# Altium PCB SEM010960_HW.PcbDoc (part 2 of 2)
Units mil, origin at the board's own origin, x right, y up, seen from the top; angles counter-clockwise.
Board outline 2559.06 x 1889.76 mil, 2 copper layers (Top Layer, Bottom Layer), stack 62 mil thick; 97 components, 58 nets, 246 pads, 75 vias.
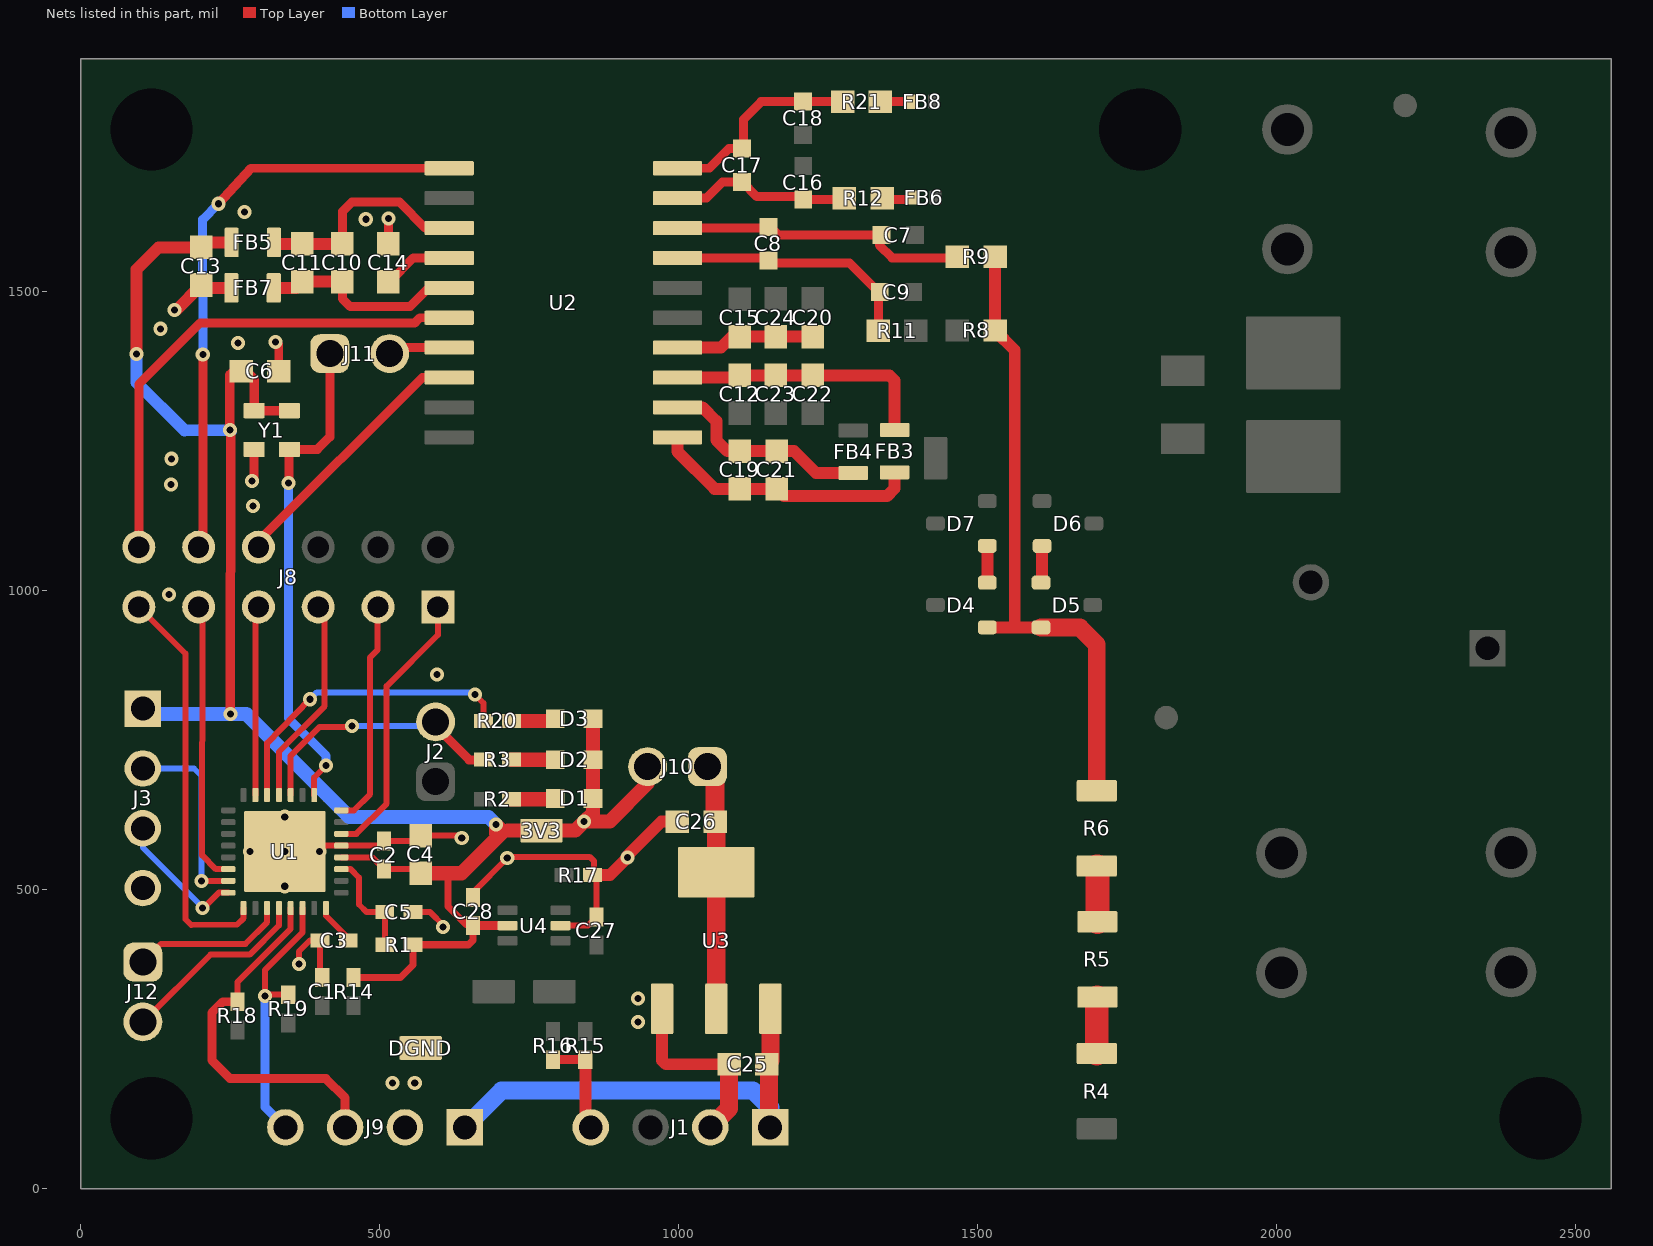
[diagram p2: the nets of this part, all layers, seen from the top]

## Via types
v1: diameter 23.62, hole 11.81, Top Layer to Bottom Layer, 58 vias
v2: diameter 39.37, hole 19.68, Top Layer to Bottom Layer, 12 vias
v3: diameter 23.62, hole 11.81, Top Layer to Bottom Layer, tented both sides, 5 vias

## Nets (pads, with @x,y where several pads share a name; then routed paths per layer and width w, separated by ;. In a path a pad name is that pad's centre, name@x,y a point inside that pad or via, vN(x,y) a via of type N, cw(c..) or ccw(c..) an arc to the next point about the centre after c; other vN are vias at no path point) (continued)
ADC_DVDD: C10.1 C11.2 FB5.1 U2.13 | length 372.5
  Top Layer w10: FB5.1@322.96,1582.83 FB5.1@325.47,1580.32
  Top Layer w15: C10.1@437.16,1580.32 437.16,1634.28 453.14,1650.26 532.82,1650.26 576.17,1606.91 U2.13@615.89,1606.91
  Top Layer w20: FB5.1@325.47,1580.32 C11.2@370.41,1580.32 C10.1@437.16,1580.32
ADC_SCLK: J8.8 U2.18 | length 442.1
  Top Layer w15: J8.8@296.88,1073.2 296.88,1082.81 570.98,1356.91 U2.18@615.89,1356.91
AMC_CLKIN: J11.2 U2.17 | length 106.5
  Top Layer w10: U2.17@613.92,1404.94 U2.17@615.89,1406.91
  Top Layer w15: J11.2@516.29,1396.93 526.27,1406.91 U2.17@615.89,1406.91
AMC_CS0: J8.1 U1.6 | length 461.2
  Top Layer w10: U1.6@435.43,593.76 460.76,593.76 511.4,644.39 511.4,840.9 596.88,926.38 J8.1@596.88,973.2
AMC_D\R\D\Y\: J8.12 U2.16 | length 837.3
  Top Layer w15: J8.12@96.88,1073.2 96.88,1345.32 199.88,1448.33 558.17,1448.33 559.07,1449.23 559.18,1449.23 566.85,1456.91 U2.16@615.89,1456.91
AMC_D\R\D\Y\0: J8.11 U1.25 | length 677.2
  Top Layer w10: J8.11@96.88,973.2 174.95,895.14 174.95,450.95 184.51,441.39 261.07,441.8 272.05,452.78 U1.25@272.05,469.74
AMC_SYNC_RESET: J8.10 U2.11 | length 1004
  Top Layer w15: J8.10@196.88,1073.2 203.84,1080.16 v1(203.84,1395.2) v1@203.57,1394.93 ; v1(230.06,1647.5) 284.34,1706.91 U2.11@615.89,1706.91
  Bottom Layer w15: v1@206.26,1392.77 v1(203.84,1395.2) 203.84,1416.57 203.59,1620.97 v1(230.06,1647.5)
AMC_SYNC_RESET0: J8.9 U1.22 | length 471.6
  Top Layer w10: J8.9@196.88,973.2 203.57,966.52 203.57,938.7 202.64,557.77 225.7,534.7 U1.22@246.46,534.7
DCDC_HGND: C19.2 C21.1 FB4.1 U2.2 | length 357.6
  Top Layer w20: U2.2@997.78,1306.91 1039.55,1306.91 1062.59,1283.86 1062.59,1252.34 1081.14,1233.79 C19.2@1101.57,1233.79 C21.1@1163.8,1233.79 1192.71,1233.79 1229.13,1197.37 FB4.1@1291.55,1197.37
DCDC_OUT: C19.1 C21.2 FB3.1 U2.1 | length 451.3
  Top Layer w10: C19.1@1100.23,1169.46 C19.1@1101.57,1170.8
  Top Layer w20: U2.1@997.78,1256.91 997.78,1232.92 1059.9,1170.8 1098.9,1170.8 C19.1@1100.23,1169.46 ; C19.1@1101.57,1170.8 C21.2@1163.8,1170.8 1176.03,1158.56 1348.04,1158.56 1360.91,1171.43 FB3.1@1360.91,1198.36
DGND: C1.2 C2.2 C3.1 C4.1 C5.2 C6.2 C13.1 C14.2 C25.2 C26.2 C27.2 C28.2 DGND.1 FB7.2 J1.2 J3.4 J9.2 R17.1 U1.5 U1.33 U3.1 U4.2 Y1.2 | length 1711.5
  Top Layer w10: v1(156.26,1469.6) v1@159.47,1469.6 ; C13.1@201.52,1511.65 C13.1@206.26,1506.91 ; v3(282.87,564.23) v3(340.94,622.3) ; v1(364.43,376.01) 364.43,396.97 382.77,415.31 C3.1@399.87,415.31 399.87,357.34 C1.2@403.54,353.67 ; v3(399.02,564.23) 408.86,574.07 U1.5@435.43,574.07 498.9,574.07 C2.2@506.78,581.95 559.28,581.95 C4.1@568.12,590.78 632.61,590.78 v1(636.88,586.52) ; C5.2@555.4,462.82 584.13,462.82 v1@606.48,440.47 ; v1@600.06,438.18 v1@611.11,438.18 ; C28.2@655.94,487.46 655.94,496.3 v1(712.97,553.34) 715.08,555.44 850.95,555.44 857.75,548.63 857.75,527.25 R17.1@855.34,524.84 862.2,517.97 C27.2@862.2,454.95 847.64,440.38 U4.2@802.02,440.38
  Top Layer w15: v1(285.83,1183.59) 289.62,1187.39 Y1.2@289.62,1236.61 ; v1(325.47,1416.57) 330.86,1411.17 C6.2@330.86,1367.63 ; C14.2@514.1,1580.32 v1(514.1,1622.96)
  Top Layer w19.68: R17.1@855.34,524.84 884.69,524.84 v1(914.24,554.39) 914.24,558.01 970.51,614.27 C26.2@1005.61,614.27
  Top Layer w20: v1@159.47,1469.6 C13.1@201.52,1511.65 ; C13.1@206.26,1506.91 FB7.2@251.55,1506.91 ; U3.1@972.04,301.14 972.04,214.71 978.33,208.42 C25.2@1084.11,208.42
  Top Layer w30: J1.2@1052.59,92.71 J1.2@1052.59,102.93 1084.11,134.44 C25.2@1084.11,204.54
  other v1: 520.98,177.22 558.3,177.22 931.38,279.35 931.38,318.23 605.59,438.18 595.38,860.16 147.33,994.09 287.78,1142.31 150.66,1178.04 151.6,1221 262.44,1414.66 133.07,1438.39 476.44,1621.64 273.68,1633.99
  other v3: 340.94,506.16 340.94,564.23
DGND_AMC: C10.2 C11.1 FB7.1 U2.15 | length 344.7
  Top Layer w15: C10.2@437.16,1517.33 437.19,1488.84 450.43,1475.61 550.22,1475.61 581.52,1506.91 U2.15@615.89,1506.91
  Top Layer w20: FB7.1@322.42,1506.91 359.99,1506.91 C11.1@370.41,1517.33 C10.2@437.16,1517.33
GLED: D1.1 R2.2 | length 73.5
  Top Layer w10: D1.1@791.85,651.64 D1.1@793.25,653.05
  Top Layer w23.62: R2.2@720.32,651.64 D1.1@791.85,651.64
HLDO_IN: C12.2 C22.1 C23.1 FB3.2 U2.3 | length 459.6
  Top Layer w10: C12.2@1107.52,1356.91 C12.2@1110.37,1354.06 ; C22.1@1224.17,1360.57 C22.1@1224.41,1360.32
  Top Layer w20: U2.3@997.78,1356.91 C12.2@1107.52,1356.91 ; C12.2@1101.57,1360.57 1163.8,1360.57 C22.1@1224.17,1360.57 1352.03,1360.57 1360.91,1351.69 FB3.2@1360.91,1269.22
HLDO_OUT: C15.2 C20.1 C24.1 U2.4 | length 242.2
  Top Layer w10: C24.1@1158.15,1424.51 1158.66,1425.02 C24.1@1165.81,1425.02 ; C20.1@1219.72,1425.02 C20.1@1220.11,1425.41
  Top Layer w20: U2.4@997.78,1406.91 1070.23,1406.91 1088.34,1425.02 C15.2@1101.57,1425.02 1101.96,1425.41 C24.1@1162.23,1425.41 1220.11,1425.41 C20.1@1223.92,1425.41
IN1: C17.2 C18.2 R21.2 U2.10 | length 350.6
  Top Layer w15: U2.10@997.78,1706.91 1050.94,1706.91 1084.15,1740.12 C17.2@1105.92,1740.12 1108.23,1742.43 1108.23,1788.71 1137.69,1818.18 C18.2@1207.7,1818.18 R21.2@1274.02,1818.18 R21.2@1275.22,1818.18
IP1: C16.1 C17.1 R12.2 U2.9 | length 305.5
  Top Layer w15: U2.9@997.78,1656.91 1045.88,1656.91 1073.09,1684.12 C17.1@1105.92,1684.12 1130.59,1659.44 1203.07,1659.44 C16.1@1207.99,1654.52 1279.47,1654.52 R12.2@1279.7,1654.75
LMK_CLKOUT: J11.1 U1.10 Y1.3 | length 824.4
  Top Layer w10: U1.10@390.16,658.72 390.16,687.96 v1(409.96,707.77)
  Top Layer w15: v1(346.88,1180.64) 348.38,1182.14 348.38,1229.11 355.88,1236.61 395.33,1236.61 416.29,1257.57 J11.1@416.29,1396.93
  Bottom Layer w15: v1(346.88,1180.64) 346.88,787.32 409.96,724.24 v1(409.96,707.77)
M_BUS: J1.4 R15.2 R16.2 | length 171.1
  Top Layer w15: R16.2@789.37,216.09 R15.2@843.53,216.09
  Top Layer w20: R15.2@843.53,216.09 843.53,111.99 J1.4@852.59,102.93
MCU_Status: R20.1 U1.14 | length 521.3
  Top Layer w10: U1.14@311.42,658.72 311.42,745.39 v1(383.04,818.9) ; v1(658.81,826.82) 673.08,812.54 R20.1@673.08,782.68
  Bottom Layer w10: v1(383.04,818.9) 394.5,830.36 655.27,830.36 v1(658.81,826.82)
NetC14_1: C14.1 U2.14 | length 118.2
  Top Layer w10: C14.1@514.1,1517.33 C14.1@516.23,1517.33
  Top Layer w15: C14.1@516.23,1517.33 555.81,1556.91 U2.14@615.89,1556.91
NetD3_1: D3.1 R20.2 | length 74.4
  Top Layer w23.62: R20.2@720.32,782.68 789.72,782.68 D3.1@793.25,786.21
NetD4_1: D4.1 D5.2 R6.2 R8.2 R9.1 | length 1072.9
  Top Layer w20: D4.1@1515.87,939.03 1561.75,939.03 ; R9.1@1528.77,1558.67 R8.2@1528.77,1435.59 1561.75,1402.61 1561.75,939.03 ; D5.2@1605.59,939.03 1561.75,939.03
  Top Layer w30: D5.2@1605.59,939.03 1670.55,939.03 1698.88,910.7 R6.2@1698.88,665.89
NetD4_2: D4.2 D7.1 | length 61.5
  Top Layer w20: D4.2@1515.87,1013.84 D7.1@1515.87,1075.35
NetD5_1: D5.1 D6.2 | length 62.3
  Top Layer w10: D5.1@1605.59,1013.84 D5.1@1607.47,1015.71
  Top Layer w20: D5.1@1607.47,1015.71 D6.2@1607.47,1075.35
NetFB6_1: FB6.1 R12.1 | length 55.3
  Top Layer w15: R12.1@1335.7,1654.75 1386.79,1654.75 FB6.1@1389.74,1657.7
NetFB8_1: FB8.1 R21.1 | length 50.2
  Top Layer w15: R21.1@1337.01,1818.18 FB8.1@1387.21,1818.18
NetR4_1: R4.1 R5.2 | length 94.6
  Top Layer w39.37: R5.2@1698.88,319.64 R5.2@1699.92,320.68
  Top Layer w40: R4.1@1698.88,226.56 R5.2@1698.88,319.64
NetR5_1: R5.1 R6.1 | length 93.7
  Top Layer w39.37: R6.1@1698.88,539.91 R6.1@1699.92,538.86
  Top Layer w40: R5.1@1699.92,446.67 R6.1@1699.92,538.86
nRST: C5.1 R1.1 U1.3 | length 183.4
  Top Layer w10: U1.3@435.43,534.7 451,534.7 465.08,520.63 465.08,475.65 477.9,462.82 C5.1@508.16,462.82 R1.1@508.16,408.3
REACT: J2.2 R3.1 U1.12 | length 428.3
  Top Layer w10: U1.12@350.79,658.72 350.79,724.21 399.23,772.65 v1@444.56,772.65
  Top Layer w15: J2.2@593.26,781.01 593.26,773.44 649.08,717.62 R3.1@668.73,717.62
  Bottom Layer w10: v1(453.14,774.42) 586.67,774.42 J2.2@593.26,781.01
SPI0_PICO: J8.5 U1.13 | length 350.7
  Top Layer w10: U1.13@330.99,658.83 330.99,730.55 407.64,807.19 407.64,808.58 407.73,808.67 407.73,829.12 407.64,829.21 407.64,962.45 J8.5@396.88,973.2
SPI0_POCI: J8.3 U1.8 | length 378
  Top Layer w10: U1.8@435.43,633.13 456.71,633.13 483.74,660.15 483.74,889.05 496.2,901.51 496.2,972.52 J8.3@496.88,973.2
SPI0_SCK: J8.7 U1.15 | length 316.7
  Top Layer w10: U1.15@291.73,658.72 291.73,692.98 291.61,693.1 291.61,967.93 J8.7@296.88,973.2
SWCLK: J3.3 U1.24 | length 228.8
  Top Layer w10: v1(203.09,469.74) 205.66,469.74 205.66,470.19 230.8,495.33 U1.24@246.46,495.33
  Bottom Layer w10: J3.3@103.57,603.05 103.57,570.87 203.09,471.35 v1(203.09,469.74)
SWDIO: J3.2 U1.23 | length 323.7
  Top Layer w10: v1(201.6,515.02) 205.37,515.02 205.51,514.88 205.66,515.02 U1.23@246.46,515.02
  Bottom Layer w10: J3.2@103.57,703.05 189.07,703.05 201.6,690.53 v1(201.6,515.02)
UART_RX1_GUI: J12.2 U1.28 | length 322.8
  Top Layer w10: J12.2@104.32,279.33 216.66,391.67 282.28,391.67 331.1,440.49 U1.28@331.1,469.74
UART_RX2_HOST: J9.3 R18.1 U1.29 | length 619.7
  Top Layer w10: R18.1@257.12,308.39 R18.1@261.68,312.95 ; R18.1@262.19,321.02 262.19,346.3 350.79,434.9 U1.29@350.79,469.74
  Top Layer w15: R18.1@261.68,312.95 237.51,312.95 219.09,294.52 219.09,215.14 249.68,184.55 409.67,184.55 441.91,152.32 J9.3@441.91,102.93
UART_TX1_GUI: J12.1 U1.27 | length 259.2
  Top Layer w10: J12.1@103.57,379.33 133.78,409.54 274.88,409.54 311.42,446.08 U1.27@311.42,469.74
UART_TX2_HOST: J9.4 R19.1 U1.30 | length 447
  Top Layer w10: R19.1@346.85,324.76 309.65,324.76 v1(307.68,322.79) 307.68,365.71 370.47,428.51 U1.30@370.47,469.74
  Bottom Layer w15: v1(307.68,322.79) 307.68,137.15 J9.4@341.91,102.93
VCORE: C3.2 U1.32 | length 69.9
  Top Layer w10: U1.32@409.84,469.74 409.84,456.78 447.11,419.52 C3.2@447.11,415.31
VDD1_3V3: C26.1 J10.1 U3.2 U3.4 | length 411.1
  Top Layer w31.5: J10.1@1047.78,706.13 1060.62,693.29 C26.1@1060.62,614.27 1062.59,612.3 U3.4@1062.59,529.48 U3.2@1062.59,301.14
VDD_3V3: 3V3.1 C2.1 C4.2 C6.1 C13.2 C28.1 D1.2 D2.2 D3.2 FB5.2 J3.1 J10.2 R1.2 R14.2 U1.4 U4.5 Y1.1 Y1.4 | length 3252.7
  Top Layer w10: v1(93.25,1396.53) v1@94.53,1397.82 ; C13.2@201.52,1574.64 C13.2@209.7,1582.83 ; U1.4@435.43,554.39 487.09,554.39 C2.1@506.78,534.7 561.21,534.7 C4.2@568.12,527.79 ; C28.1@655.94,440.22 C28.1@656.11,440.38
  Top Layer w11.81: R14.2@455.94,353.67 534.54,353.67 555.4,374.52 R1.2@555.4,408.3 648.41,408.3 655.94,415.84 C28.1@655.94,440.22 ; 614.19,523.94 614.19,472.13 C28.1@644.13,442.18
  Top Layer w15: C28.1@656.11,440.38 U4.5@713.44,440.38
  Top Layer w15.75: v1@246.06,1272.04 v1(249.22,1268.88) 249.22,1361.64 260.73,1373.15 270.69,1373.15 289.62,1354.21 Y1.1@289.62,1301.57 Y1.4@348.68,1301.57 ; v1(250.08,794.49) v1@250.83,1267.29
  Top Layer w20: v1(93.25,1396.53) 93.25,1538 129.89,1574.64 C13.2@201.52,1574.64 ; C13.2@209.7,1582.83 FB5.2@252.1,1582.83
  Top Layer w23.62: C4.2@568.12,527.79 636.55,527.79 703.52,594.76 ; 694.09,594.76 v1(694.09,609.64) 704.45,599.28 ; 713.88,599.28 826.67,599.28 ; 3V3.1@770.28,599.28 826.67,599.28 ; D2.2@856.23,717.62 856.23,653.05 856.24,628.84 v1(841.67,614.27) ; D2.2@856.23,717.62 D3.2@856.24,786.21 ; J10.2@947.78,706.13 947.78,677.67 884.38,614.27 v1(841.67,614.27) ; 826.67,599.28 v1(841.67,614.27)
  Bottom Layer w20: v1(93.25,1396.53) 93.25,1348.43 173.16,1268.52 v1(249.22,1268.88) v1@250.83,1267.29
  Bottom Layer w23.62: J3.1@103.57,803.05 112.13,794.49 v1(250.08,794.49) 276.45,794.49 448.82,622.13 681.6,622.13 v1(694.09,609.64)
VIN: C25.1 J1.1 J9.1 U3.3 | length 784.3
  Top Layer w10: C25.1@1147.1,208.42 C25.1@1153.14,214.46
  Top Layer w20: C25.1@1147.1,208.42 C25.1@1150.56,204.97 ; J1.1@1150.56,104.96 J1.1@1152.59,102.93
  Top Layer w30: J1.1@1150.56,104.96 C25.1@1150.56,204.97 ; C25.1@1153.14,214.46 U3.3@1153.14,301.14
  Bottom Layer w30: J9.1@641.91,102.93 703.67,164.69 1124.11,164.69 1152.59,136.21
  Bottom Layer w31.5: J1.1@1152.59,102.93 1152.59,136.21
VN2: C8.2 C9.2 R11.2 U2.7 | length 425.3
  Top Layer w15: U2.7@997.78,1556.91 1141.82,1556.91 1149.9,1548.83 1285.17,1548.83 1334.09,1499.91 1334.09,1435.59 R11.2@1333.36,1434.86
VP2: C7.1 C8.1 R9.2 U2.8 | length 504
  Top Layer w15: U2.8@997.78,1606.91 1144.99,1606.91 1149.9,1611.82 1166.7,1595.02 1335.41,1595.02 1335.41,1578.23 1356.73,1556.91 1459.91,1556.91 R9.2@1465.06,1562.05
YLED: D2.1 R3.2 | length 73.1
  Top Layer w23.62: R3.2@720.32,717.94 720.64,717.62 D2.1@793.24,717.62
pads on no net: D4.3 D5.3 D6.1 D7.2 FID1.1 FID2.1 J1.3 MH1.1 MH2.1 MH3.1 MH4.1 U1.1 U1.2 U1.7 U1.9 U1.16 U1.17 U1.18 U1.19 U1.20 U1.21 U1.26 U1.31

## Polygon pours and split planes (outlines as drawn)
DGND on Top Layer "TOP_LAYER_DGND_P033" (solid, remove dead copper, pour order 33): 38.81,1558.32 305.12,1824.63 644.07,1824.63 644.07,1101.79 928.15,817.71 1053.64,817.71 1291.55,579.8 1291.55,39.96 323.61,39.96 38.81,324.76
A_Netural_IN on Top Layer "TOP_LAYER_A_NETURAL_IN_P031" (solid, remove dead copper, pour order 31): 981.4,1846.72 1452.87,1846.72 1452.87,1716.97 1579.52,1716.97 1701.01,1595.48 1701.01,1322.55 1747.17,1276.4 2102.36,1276.4 2102.36,904.09 1448.3,904.09 1210.08,1142.31 1060.97,1142.31 978.69,1224.59 978.69,1842.2 983.21,1846.72
VDD1_3V3 on Top Layer "TOP_LAYER_VDD1_3V3_P027" (solid, remove dead copper, pour order 27): 1000,738.44 1001.15,739.6 1093.95,739.6 1093.95,589.53 1090.15,585.73 1092.55,583.33 1128.77,583.33 1128.77,401.75 1127.02,403.5 1000,403.5
VDD_3V3 on Top Layer "TOP_LAYER_VDD_3V3_P026" (solid, remove dead copper, pour order 26): 816.86,745.18 983.85,745.18 983.85,684.47 882.7,583.33 674.56,583.33 674.56,628.29 677.36,625.49 816.87,625.49 816.87,745.18
A_Netural_OUT on Top Layer "TOP_LAYER_A_NETURAL_OUT_P004" (solid, remove dead copper, pour order 4): 1781.5,1642.74 1956.5,1817.74 1956.5,1832.72 2102.36,1832.72 2102.36,1346.64 1781.5,1346.64
DGND on Bottom Layer "BOTTOM_LAYER_DGND_P038" (solid, remove dead copper, pour order 38): 30.89,1522.08 328.48,1819.67 328.48,1824.63 644.07,1824.63 645.16,1823.54 645.16,1131.58 675.69,1101.05 675.69,1072.28 928.24,819.72 1051.62,819.72 1291.55,579.8 1291.55,39.96 323.61,39.96 46.89,316.68 46.89,1511.53 30.89,1527.53
A_Netural_IN on Bottom Layer "BOTTOM_LAYER_A_NETURAL_IN_P032" (solid, remove dead copper, pour order 32): 981.4,1846.72 982.74,1845.38 1511.52,1845.38 1748.72,1608.18 1748.72,1277.95 1747.17,1276.4 2102.36,1276.4 2102.36,904.09 1448.3,904.09 1210.08,1142.31 1074.3,1142.31 1074.3,1143.28 983.21,1234.37 983.21,1846.72
A_Netural_OUT on Bottom Layer "BOTTOM_LAYER_A_NETURAL_OUT_P014" (solid, remove dead copper, pour order 14): 1781.5,1641.74 1972.48,1832.72 2102.36,1832.72 2102.36,1346.64 1781.5,1346.64

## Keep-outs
Keep-Out Layer:
  text ".Layer_Name" at 577,-858.49 h60

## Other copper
Top Layer:
  pour cut-out: 265.75,1328.74 267.89,1330.89 384.98,1330.89 384.98,1202.93 385.47,1202.45 385.31,1202.29 266.09,1202.29 266.09,1328.09
  text ".Layer_Name" at 577,-858.49 h60
Bottom Layer:
  pour cut-out: 267.89,1330.89 384.98,1330.89 384.98,1202.93 384.34,1202.29 266.09,1202.29 266.09,1329.08
  text ".Layer_Name" at 577,-858.49 h60

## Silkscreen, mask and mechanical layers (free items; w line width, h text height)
Top Overlay:
  lines w10: 500.81,791.44 500.81,767.82 525.53,743.1 ; 1261.38,1399.8 1417.8,1398.07 1441.01,1374.86 ; 1411.85,1462.06 1417.41,1462.06 1433.79,1478.45
  text "Rev_A" at 881.99,1791.6 h60
  text "TIDA-010960" at 291.61,1781.85 h108.27
  text "3V3" at 11.94,867.88 h60 r270
  text "REACT" at 410.26,844.18 h50
  text "ACT" at 424.21,800.75 h50
  text "DIO" at 11.69,758.29 h60 r270
  text "CLK" at 11.69,654.41 h60 r270
  text "GND" at 11.69,543.66 h60 r270
  text "TX1" at 11.6,418.17 h60 r270
  text "RX1" at 11.6,311.72 h60 r270
  text "GND" at 502.14,12.57 h60
  text "VIN" at 626.33,12.57 h60
  text "MBUS" at 786.04,12.57 h60
  text "GND" at 984.47,12.57 h60
  text "VIN" at 1119.02,12.57 h60
  text "TX2" at 286.88,12.49 h60
  text "RX2" at 397.76,12.49 h60
  text ".Layer_Name" at 577,-858.49 h60
Bottom Overlay:
  text ".Layer_Name" at 577,-858.49 h60
Top Paste:
  text ".Layer_Name" at 577,-858.49 h60
Bottom Paste:
  text ".Layer_Name" at 577,-858.49 h60
Top Solder:
  text ".Layer_Name" at 577,-858.49 h60
  text ".Layer_Name" at 577,-858.49 h60
Bottom Solder:
  text ".Layer_Name" at 577,-858.49 h60
Drill Guide:
  text ".Layer_Name" at 577,-858.49 h60
M1 Board Outline:
  the board outline again, w10
  text ".Layer_Name" at 577,-858.49 h60
M2 Board Dimensions:
  rectangle: 0,-275 125,-150
  rectangle: 125,-400 500,-275
  lines w7: 0,-275 1000,-275 ; 125,-400 125,-150 ; 250,-400 250,-150 ; 500,-400 500,-150 ; 750,-400 750,-150 ; 0,-400 1000,-400 1000,-150 0,-150 0,-400
  text ".Layer_Name" at 577,-858.49 h60
M3 3D STEP Top:
  text ".Layer_Name" at 577,-858.49 h60
M4 3D STEP Bottom:
  text ".Layer_Name" at 577,-858.49 h60
M5 Assembly Top:
  lines w10: -292,-930.17 6308,-930.17 ; -292,-726.83 6310,-726.83 ; -292,-523.5 -292,-1133.5 3713,-1133.5 6310,-1133.5 6310,-523.5 -291.5,-523.5 -291.5,-1133.5 1284,-1133.5 ; 2173,-1133.5 2173,-523.5 ; 3440,-726.83 3440,-523.5 ; 4280,-726.83 4280,-523.5 ; 4902,-1140 4902,-937.17
  text ".VariantName" at 1618.2,-275 h60
  text "COMPONENTS MARKED 'DNP' SHOULD NOT BE POPULATED." at 2233.07,-433.07 h60
  text "ASSEMBLY VARIANT:" at 1153,-434 h60
  text "PCB VIEWED FROM TOP SIDE" at -228.5,-655.67 h60
  text "BOARD #:" at 2248,-655.67 h60
  text ".PRJ_Number" at 2793.5,-655.67 h60
  text "REV:" at 3638,-655.67 h60
  text ".PCB_Rev" at 3929.5,-655.67 h60
  text "SVN REV:" at 4476,-655.67 h60
  text ".VersionControl_RevNumber" at 4982,-655.67 h60
  text "TID #:" at 2248,-859 h60
  text ".TID" at 2793.5,-859 h60
  text "PLOT NAME =" at -228.5,-1064.34 h60
  text ".plot_File_Name" at 577,-1064.34 h60
  text "GENERATED    :" at 2250,-1064.34 h60
  text ".Print_Date" at 3119.5,-1064.34 h60
  text ".Print_Time" at 3848.5,-1064.34 h60
  text "TEXAS INSTRUMENTS" at 5113,-1064.34 h60
M6 Assembly Bottom:
  lines w10: -292.5,-727.33 6309.5,-727.33 ; -290.5,-930.67 6309.5,-930.67 ; 1115.5,-1140.5 1115.5,-937.67 ; 1737.5,-727.33 1737.5,-524 ; 2577.5,-727.33 2577.5,-524 ; 3539.38,-1135.29 3539.38,-525.29 ; 4733.5,-1134 6309,-1134 6309,-524 -292.5,-524 -292.5,-1134 2304.5,-1134 6309.5,-1134 6309.5,-524
  text "COMPONENTS MARKED 'DNP' SHOULD NOT BE POPULATED." at 5324.8,-265.75 h60
  text ".VariantName" at 5058,-434 h60
  text "ASSEMBLY VARIANT:" at 6097,-434 h60
  text ".VersionControl_RevNumber" at 1035.5,-656.17 h60
  text "SVN REV:" at 1541.5,-656.17 h60
  text ".PCB_Rev" at 2088,-656.17 h60
  text "REV:" at 2379.5,-656.17 h60
  text ".PRJ_Number" at 3224,-656.17 h60
  text "BOARD #:" at 3769.5,-656.17 h60
  text "PCB VIEWED FROM BOTTOM SIDE" at 6246,-656.17 h60
  text ".TID" at 3224,-859.5 h60
  text "TID #:" at 3769.5,-859.5 h60
  text "TEXAS INSTRUMENTS" at 904.5,-1064.84 h60
  text ".Print_Time" at 2169,-1064.84 h60
  text ".Print_Date" at 2898,-1064.84 h60
  text "GENERATED    :" at 3767.5,-1064.84 h60
  text ".plot_File_Name" at 5440.5,-1064.84 h60
  text "PLOT NAME =" at 6246,-1064.84 h60
M9 Title Sheet:
  drawing of 57 lines, arcs and shapes, not listed
  text "1" at 739.84,8036.5 h70
  text "2" at 3235.5,8036.5 h70
  text "3" at 5724.84,8036.5 h70
  text "4" at 8231.51,8036.5 h70
  text "5" at 10730.5,8036.5 h70
  text "6" at 13235.5,8036.5 h70
  text "A" at -416.5,6893.5 h70
  text "A" at 14383.5,6893.5 h70
  text "B" at -416.5,4513.5 h70
  text "B" at 14383.5,4513.5 h70
  text "C" at -416.5,2138.5 h70
  text "C" at 14383.5,2138.5 h70
  text "PROJECT TITLE:" at 11343.5,277.5 h45
  text ".PRJ_Title" at 11393.5,144.17 h70
  text "DESIGNED FOR:" at 11343.5,-23.5 h45
  text ".PRJ_Customer" at 11393.5,-163.5 h70
  text "D" at -416.5,-231.5 h70
  text "D" at 14383.5,-231.5 h70
  text "FILE NAME:" at 11343.5,-323.5 h45
  text ".PCB_File_Name_No_Path" at 11393.5,-443.5 h70
  text "Texas Instruments (TI) and/or its licensors do not warrant the accuracy or completeness of this specification" at 6374,-605.34 h45
  text "ENGINEER:" at 11343.5,-613.5 h45
  text "LAYOUT BY:" at 12848.5,-613.5 h45
  text "or any information contained therein. TI and/or its licensors do not warrant that this design will meet" at 6329.01,-718 h45
  text ".PRJ_Engineer" at 11393.5,-768.49 h70
  text "Joe Wang" at 12899,-768.49 h70
  text "the specifications, will be suitable for your application or fit for any particular purpose, or will operate in" at 6329.01,-830.67 h45
  text ".Layer_Name" at 577,-858.49 h60
  text "ALTIUM DESIGNER VERSION:" at 12848.5,-923.5 h45
  text "an implementation. TI and/or its licensors do not warrant that the design is production worthy. You should" at 6329.01,-943.33 h45
  text "completely validate and test your design implementation to confirm the system functionality for your application." at 6374,-1056 h45
  text ".print_Scale" at 11393.5,-1056.83 h70
  text ".Application_BuildNumber" at 12899,-1056.83 h70
  text "1" at 739.84,-1263.5 h70
  text "2" at 3235.5,-1263.5 h70
  text "3" at 5724.84,-1263.5 h70
  text "4" at 8231.51,-1263.5 h70
  text "5" at 10730.5,-1263.5 h70
  text "6" at 13235.5,-1263.5 h70
M10 Fab Notes:
  drawing of 189 lines, arcs and shapes, not listed
  text "DESIGN INFORMATION" at 12382.02,6356.17 h60
  text "MIN. TRACK WIDTH:" at 11737.46,6224.05 h60
  text "8" at 12833.7,6224.05 h60
  text "MIL" at 12988.46,6224.05 h60
  text "7.874" at 12667.32,6102.36 h60
  text "MIN. CLEARANCE:" at 11737.46,6099.92 h60
  text "MIL" at 12988.46,6099.92 h60
  text "MIN. VIA PAD SIZE:" at 11737.46,5975.8 h60
  text "24" at 12803.71,5975.8 h60
  text "MIL" at 12988.46,5975.8 h60
  text "0.05mm (2MIL)" at 12432.46,5845.9 h60
  text "MINIMUM ANNULAR RING" at 11408.23,5837.67 h60
  text "EXTERNAL" at 13140.46,5837.67 h60
  text "PER" at 11608.23,5727.55 h60
  text "IPC-D-275 CLASS 2 LEVEL C" at 11828.23,5727.54 h60
  text "MIL, HOLES" at 13316.46,5627.07 h60
  text "+/-" at 12924,5618.48 h60
  text "+/-" at 13778,5618.48 h60
  text "REGISTRATION TOLERANCES:" at 11408.23,5617.42 h60
  text "METAL" at 12608,5617.42 h60
  text "5" at 13184.2,5617.42 h60
  text "3" at 14017.2,5617.42 h60
  text "MIL" at 14133.46,5617.42 h60
  text "HOLE SIZE TOLERANCE (UNLESS OTHERWISE SPECIFIED):" at 11408.23,5519.1 h60
  text "+/-" at 13778,5516.23 h60
  text "3" at 14017.2,5515.17 h60
  text "MIL" at 14133.46,5515.17 h60
  text "MATERIAL:" at 11333.46,5377.52 h60
  text "FR-4 High Tg" at 12319.9,5249 h60
  text "X" at 12175.46,5241.01 h60
  text "FR-4" at 11754.46,5236.49 h60
  text "OTHER" at 13242.46,5236.49 h60
  text "62 MIL (1.6mm) +/-10%" at 12074.56,5093.46 h60
  text "X" at 11954.46,5091.01 h60
  text "THICKNESS:" at 11408.23,5085.24 h60
  text "OTHER" at 13359.46,5085.24 h60
  text "TOLERANCE:" at 11408.23,4946.92 h60
  text "X" at 12256.46,4946.92 h60
  text "ANSI IPC-6012 TYPE 3 CLASS 2" at 12434.48,4946.92 h60
  text "OTHER +/-" at 12434.46,4802.73 h60
  text "BOW & TWIST:" at 11408.23,4657.54 h60
  text "X" at 12256.46,4657.54 h60
  text "ANSI IPC-6012 TYPE 3 CLASS 2" at 12434.48,4657.54 h60
  text "OTHER +/-" at 12434.46,4510.85 h60
  text "DRILLING:" at 11333.46,4380.23 h60
  text "NC_DRILL FILES" at 13094.46,4275.04 h60
  text "REFERENCE:" at 11408.23,4271.1 h60
  text "X" at 12065.46,4271.01 h60
  text "AS SHOWN" at 12243.46,4271.1 h60
  text "X" at 12966.46,4271.1 h60
  text "OTHER" at 13392.46,4128.85 h60
  text "PTH COPPER THICKNESS:" at 11407.91,4125.32 h60
  text "X" at 12547.14,4125.32 h60
  text "20-30 um" at 12675.14,4125.32 h60
  text "BOARD FINISH:" at 11333.46,3977.73 h60
  text "SILKSCREEN:" at 11488.68,3867.6 h60
  text "X" at 12446.46,3867.6 h60
  text "TOP" at 12563.46,3867.6 h60
  text "X" at 12956.46,3867.6 h60
  text "BOTTOM" at 13074.46,3867.6 h60
  text "SILKSCREEN COLOR:" at 11488.68,3712.41 h60
  text "X" at 12445.46,3712.41 h60
  text "WHITE" at 12563.46,3712.41 h60
  text "OTHER" at 13074.46,3712.41 h60
  text "X" at 12576.46,3568.96 h60
  text "GREEN" at 12694.46,3568.96 h60
  text "OTHER" at 13312.46,3568.96 h60
  text "SOLDER RESIST COLOR:" at 11488.68,3562.1 h60
  text "X" at 12576.46,3414.71 h60
  text "MATTE" at 12694.46,3414.71 h60
  text "SEMI-GLOSS" at 13312,3414.07 h60
  text "IMMERSION GOLD (ENIG)" at 12394.46,3241.94 h60
  text "ENEPIG" at 13732,3234.72 h60
  text "SURFACE FINISH:" at 11333.46,3233.72 h60
  text "X" at 12216.46,3233.72 h60
  text "IMM. TIN/SILVER OR EQUIV" at 11663,3096.4 h60
  text "OTHER" at 13094.46,3092.47 h60
  text "ARRAY/PANEL:" at 11333.46,2937.09 h60
  text "CUT AND TRIM PER M1 BOARD OUTLINE" at 12394.46,2928.87 h60
  text "N.C. ROUTE" at 12394.46,2792.9 h60
  text "X" at 13082.46,2792.9 h60
  text "V. SCORE" at 13260.46,2792.9 h60
  text "CERTIFICATION:" at 11333.46,2663.77 h60
  text "MATERIALS AND WORKMANSHIP FOR ALL PCBS" at 12058.46,2663.77 h60
  text "TO MEET OR EXCEED THE REQUIREMENTS OF:" at 12058.46,2569.71 h60
  text "X" at 11695.97,2441.08 h60
  text "ANSI IPC-A-600F CLASS ->" at 11823.96,2441.08 h60
  text "X" at 13471.97,2441.08 h60
  text "2" at 13581.96,2441.08 h60
  text "1" at 13266.96,2439.58 h60
  text "3" at 13935.96,2439.58 h60
  text "X" at 12507.97,2293.39 h60
  text "RoHS" at 12635.96,2293.39 h60
  text "OTHER" at 13280.36,2293.39 h60
  text "PER ORDER" at 13677.42,2293.39 h60
  text "ALL BOARDS MUST MEET OR EXCEED UL94-V0 REQUIREMENTS." at 11361,2139.57 h60
  text "PCB MUST BEAR THE UL94V-0 UL REGISTERED MATERIAL ID NUMBER" at 11361,2023.5 h60
  text "ADDITIONAL REQUIREMENTS:" at 11333.46,1854.08 h60
  text "MICROSECTION:" at 11408.23,1746.95 h60
  text "YES" at 12313.96,1746.95 h60
  text "REQUIRED" at 13175.46,1602.62 h60
  text "BARE BOARD ELEC. TEST:" at 11408.23,1599.76 h60
  text "NONE" at 12713.96,1599.76 h60
  text "X" at 13057.46,1599.76 h60
  text "PER ORDER" at 13767.46,1599.76 h60
  text "XX MIL VIAS REQUIRE NON-CONDUCTIVE FILL AND PLANARIZE" at 11576.38,1394.82 h59
  text "XX MIL VIAS REQUIRE CONDUCTIVE FILL AND PLANARIZE" at 11584.38,1290.84 h60
  text "OUTER XX MIL TRACES REQUIRE 50 OHM SINGLE-ENDED IMPEDANCE" at 11583.39,1127.46 h58
  text "LAYER 2 & 3 (INNER LAYERS) XX MIL WIDE, XX MIL SPACE / TRACES REQUIRE 100 OHM DIFFERENTIAL IMPEDANCE" at 11575.39,891.74 h60
  text ".Layer_Name" at 577,-858.49 h60
M11 Gerber Information:
  lines w10: -292,-930.17 6308,-930.17 ; -292,-726.83 6310,-726.83 ; -292,-523.5 -292,-1133.5 3713,-1133.5 6310,-1133.5 6310,-523.5 -291.5,-523.5 -291.5,-1133.5 1284,-1133.5 ; 2173,-1133.5 2173,-523.5 ; 3440,-726.83 3440,-523.5 ; 4280,-726.83 4280,-523.5 ; 4902,-1140 4902,-937.17
  text "ALL ARTWORK VIEWED FROM TOP SIDE" at -228.5,-655.67 h60
  text "BOARD #:" at 2248,-655.67 h60
  text "TIDA-010960" at 2736.22,-655.67 h60
  text "REV:" at 3638,-655.67 h60
  text "A" at 3929.5,-655.67 h60
  text "SVN REV:" at 4476,-655.67 h60
  text ".VersionControl_RevNumber" at 4982,-655.67 h60
  text "LAYER NAME =" at -228.5,-858.49 h60
  text "TID #:" at 2248,-859 h60
  text ".TID" at 2793.5,-859 h60
  text "PLOT NAME =" at -228.5,-1064.34 h60
  text ".plot_File_Name" at 577,-1064.34 h60
  text "GENERATED    :" at 2250,-1064.34 h60
  text ".Print_Date" at 3119.5,-1064.34 h60
  text ".Print_Time" at 3848.5,-1064.34 h60
  text "TEXAS INSTRUMENTS" at 5113,-1064.34 h60
M12 Stackup:
  drawing of 191 lines, arcs and shapes, not listed
  text "Layer" at 9821.59,7874.94 h60
  text "Name" at 10231.51,7874.94 h60
  text "Material" at 11161.25,7874.94 h60
  text "Thickness" at 12021.02,7874.94 h60
  text "Constant" at 12670.85,7874.94 h60
  text "Board Layer Stack" at 13240.71,7874.94 h60
  text "Top Overlay" at 10231.51,7754.94 h60
  text "Top Solder" at 10231.51,7634.94 h60
  text "Solder Resist" at 11161.25,7634.94 h60
  text "0.40mil" at 12021.02,7634.94 h60
  text "3.5" at 12670.85,7634.94 h60
  text "1" at 9821.59,7514.94 h60
  text "Top Layer" at 10231.51,7514.94 h60
  text "1.40mil" at 12021.02,7514.94 h60
  text "Dielectric1" at 10231.51,7394.94 h60
  text "FR-4 High Tg" at 11161.25,7394.94 h60
  text "59.20mil" at 12021.02,7394.94 h60
  text "4.8" at 12670.85,7394.94 h60
  text "2" at 9821.59,7274.94 h60
  text "Bottom Layer" at 10231.51,7274.94 h60
  text "1.40mil" at 12021.02,7274.94 h60
  text "Bottom Solder" at 10231.51,7154.94 h60
  text "Solder Resist" at 11161.25,7154.94 h60
  text "0.40mil" at 12021.02,7154.94 h60
  text "3.5" at 12670.85,7154.94 h60
  text "Bottom Overlay" at 10231.51,7034.94 h60
  text ".Layer_Name" at 577,-858.49 h60
M13 Component Bodies Top:
  text ".Layer_Name" at 577,-858.49 h60
M14 Component Bodies Bottom:
  text ".Layer_Name" at 577,-858.49 h60
M15 Courtyards Top:
  text ".Layer_Name" at 577,-858.49 h60
M16 Courtyards Bottom:
  text ".Layer_Name" at 577,-858.49 h60
Drill Drawing:
  circle w10: c5363.72,3290.28 r27.63
  lines w10: 5336.09,2392.42 5391.34,2392.42 5391.34,2447.67 5336.09,2447.67 5336.09,2392.42 ; 5336.09,2516.74 5391.34,2516.74 5391.34,2571.99 5336.09,2571.99 5336.09,2516.74 ; 5336.09,2641.06 5363.72,2654.87 5391.34,2641.06 5377.53,2668.68 5391.34,2696.31 5363.72,2682.5 5336.09,2696.31 5349.9,2668.68 5336.09,2641.06 ; 5336.09,2779.19 5349.9,2779.19 5349.9,2765.38 5377.53,2765.38 5377.53,2779.19 5391.34,2779.19 5391.34,2806.82 5377.53,2806.82 5377.53,2820.63 5349.9,2820.63 5349.9,2806.82 5336.09,2806.82 5336.09,2779.19 ; 5336.09,2944.95 5391.34,2944.95 5363.72,2889.7 5336.09,2944.95 ; 5336.09,3027.83 5349.9,3027.83 5363.72,3014.02 5377.53,3027.83 5391.34,3027.83 5377.53,3041.64 5391.34,3055.46 5377.53,3055.46 5363.72,3069.27 5349.9,3055.46 5336.09,3055.46 5349.9,3041.64 5336.09,3027.83 ; 5336.09,3138.34 5336.09,3152.15 5349.9,3165.96 5336.09,3179.78 5336.09,3193.59 5349.9,3193.59 5363.72,3179.78 5377.53,3193.59 5391.34,3193.59 5391.34,3179.78 5377.53,3165.96 5391.34,3152.15 5391.34,3138.34 5377.53,3138.34 5363.72,3152.15 5349.9,3138.34 5336.09,3138.34 ; 5347.14,2403.47 5380.29,2403.47 5380.29,2436.62 5347.14,2436.62 5347.14,2403.47
  lines w12: 5286,2355.12 8517.49,2355.12 ; 5286,3349.68 8517.49,3349.68 ; 5623.86,2230.8 5623.86,3474 ; 5955.86,2230.8 5955.86,3474 ; 6592.43,2230.8 6592.43,3474 ; 6851.57,2230.8 6851.57,3474 ; 7226.72,2230.8 7226.72,3474 ; 7951.05,2230.8 7951.05,3474 ; 5286,2230.8 8517.49,2230.8 8517.49,3474 5286,3474 5286,2230.8
  text "Symbol" at 5360.59,3386.98 h72
  text "Quantity" at 5661.16,3386.98 h72
  text "Finished Hole Size" at 5993.16,3386.98 h72
  text "Plated" at 6629.72,3386.98 h72
  text "Hole Type" at 6888.86,3386.98 h72
  text "Drill Layer Pair" at 7264.02,3386.98 h72
  text "Hole Tolerance" at 7988.35,3386.98 h72
  text "4" at 5661.16,3262.66 h60
  text "137.79mil (3.500mm)" at 5993.16,3262.66 h60
  text "NPTH" at 6629.72,3262.66 h60
  text "Round" at 6888.86,3262.66 h60
  text "Top Layer - Bottom Layer" at 7264.02,3262.66 h60
  text "63" at 5661.16,3138.34 h60
  text "11.81mil (0.300mm)" at 5993.16,3138.34 h60
  text "PTH" at 6629.72,3138.34 h60
  text "Round" at 6888.86,3138.34 h60
  text "Top Layer - Bottom Layer" at 7264.02,3138.34 h60
  text "12" at 5661.16,3014.02 h60
  text "19.69mil (0.500mm)" at 5993.16,3014.02 h60
  text "PTH" at 6629.72,3014.02 h60
  text "Round" at 6888.86,3014.02 h60
  text "Top Layer - Bottom Layer" at 7264.02,3014.02 h60
  text "12" at 5661.16,2889.7 h60
  text "35.43mil (0.900mm)" at 5993.16,2889.7 h60
  text "PTH" at 6629.72,2889.7 h60
  text "Round" at 6888.86,2889.7 h60
  text "Top Layer - Bottom Layer" at 7264.02,2889.7 h60
  text "2" at 5661.16,2765.38 h60
  text "39.37mil (1.000mm)" at 5993.16,2765.38 h60
  text "PTH" at 6629.72,2765.38 h60
  text "Round" at 6888.86,2765.38 h60
  text "Top Layer - Bottom Layer" at 7264.02,2765.38 h60
  text "12" at 5661.16,2641.06 h60
  text "40.00mil (1.016mm)" at 5993.16,2641.06 h60
  text "PTH" at 6629.72,2641.06 h60
  text "Round" at 6888.86,2641.06 h60
  text "Top Layer - Bottom Layer" at 7264.02,2641.06 h60
  text "8" at 5661.16,2516.74 h60
  text "45.28mil (1.150mm)" at 5993.16,2516.74 h60
  text "PTH" at 6629.72,2516.74 h60
  text "Round" at 6888.86,2516.74 h60
  text "Top Layer - Bottom Layer" at 7264.02,2516.74 h60
  text "8" at 5661.16,2392.42 h60
  text "55.12mil (1.400mm)" at 5993.16,2392.42 h60
  text "PTH" at 6629.72,2392.42 h60
  text "Round" at 6888.86,2392.42 h60
  text "Top Layer - Bottom Layer" at 7264.02,2392.42 h60
  text "121 Total" at 5661.16,2268.1 h60
  text ".Layer_Name" at 577,-858.49 h60
M17 Embedded Cavity:
  text ".Layer_Name" at 577,-858.49 h60
M18 Embedded Assembly:
  text ".Layer_Name" at 577,-858.49 h60
M19 Embedded Keepout:
  text ".Layer_Name" at 577,-858.49 h60

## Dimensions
0,-400 to 1000,-400 on M2 Board Dimensions
0,0 to 0,1889.76 on M2 Board Dimensions
0,0 to 2559.06,0 on M2 Board Dimensions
